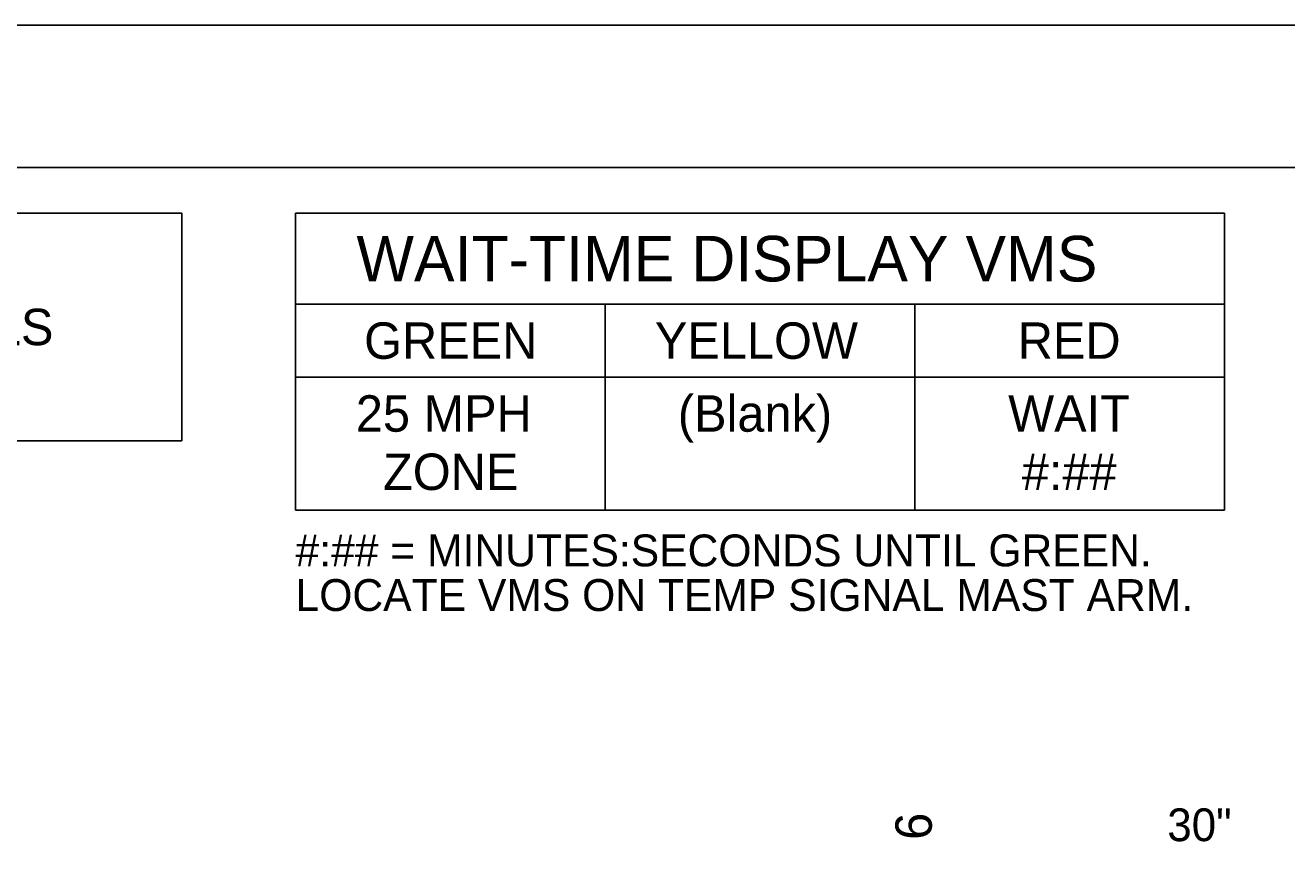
# Model space of a CAD drawing. Extents: x 99977 to 100176, y 99905 to 100011.
# Drawn here: x 100082.228 to 100084.999, y 100008.89 to 100010.687 of the extents above; entities that cross this region are included whole.
import ezdxf

# ---------------------------------------------------------------- set-up
doc = ezdxf.new("R2010")
doc.units = 0
for name, color, linetype in [('SH_GI_PlotLimits', 7, 'Continuous'), ('SH_GI_SheetBorder', 7, 'Continuous'), ('SH_TI_Tables', 7, 'Continuous'), ('TR_SN_ConstructionSigns', 7, 'Continuous'), ('TR_WZ_PortableChangeMessageSign', 7, 'Continuous'), ('TR_WZ_WorkZoneTextCurrent', 7, 'Continuous')]:
    doc.layers.add(name, color=color, linetype=linetype)

msp = doc.modelspace()

# ---------------------------------------------------------------- linework, layer by layer
at = {"layer": 'SH_GI_PlotLimits'}
msp.add_lwpolyline([(100079.0625, 99999.6875), (100096.0625, 99999.6875), (100096.0625, 100010.6875), (100079.0625, 100010.6875)], close=True, dxfattribs=at)
at = {"layer": 'SH_GI_SheetBorder'}
msp.add_line((100080, 100010.375), (100095.75, 100010.375), dxfattribs=at)
at = {"layer": 'SH_TI_Tables'}
msp.add_lwpolyline([(100080.1, 100010.275), (100082.5718, 100010.275), (100082.5718, 100009.775), (100080.1, 100009.775)], close=True, dxfattribs=at)
at = {"layer": 'TR_WZ_PortableChangeMessageSign'}
for p, q in [((100082.8218, 100010.275), (100084.8618, 100010.275)), ((100082.8218, 100009.6227), (100082.8218, 100010.275)), ((100084.8618, 100009.6227), (100084.8618, 100010.275)), ((100084.8618, 100010.075), (100082.8218, 100010.075)), ((100083.5018, 100009.6227), (100083.5018, 100010.075)), ((100084.1818, 100009.6227), (100084.1818, 100010.075)), ((100083.5018, 100009.915), (100082.8218, 100009.915)), ((100084.1818, 100009.915), (100083.5018, 100009.915)), ((100084.8618, 100009.915), (100084.1818, 100009.915)), ((100084.8618, 100009.6227), (100082.8218, 100009.6227))]:
    msp.add_line(p, q, dxfattribs=at)

# ---------------------------------------------------------------- texts
at = {"layer": 'SH_TI_Tables'}
msp.add_text('AND INTERSECTING ROADWAY DETAILS', height=0.08, rotation=360, dxfattribs=at).set_placement((100080.18, 100009.985))
at = {"layer": 'TR_SN_ConstructionSigns'}
msp.add_text('30"', height=0.072, rotation=360, dxfattribs=at).set_placement((100084.7363, 100008.8959))
at = {"layer": 'TR_WZ_PortableChangeMessageSign'}
for s, height, p in [('WAIT-TIME DISPLAY VMS', 0.1, (100082.9556, 100010.125)), ('GREEN', 0.08, (100082.9724, 100009.955)), ('YELLOW', 0.08, (100083.6109, 100009.955)), ('RED', 0.08, (100084.4078, 100009.955)), ('(Blank)', 0.08, (100083.6614, 100009.795)), ('25 MPH', 0.08, (100082.9542, 100009.795)), ('WAIT', 0.08, (100084.3868, 100009.795)), ('ZONE', 0.08, (100083.0139, 100009.667)), ('#:##', 0.08, (100084.4169, 100009.667)), ('#:## = MINUTES:SECONDS UNTIL GREEN.', 0.07, (100082.8218, 100009.4993)), ('LOCATE VMS ON TEMP SIGNAL MAST ARM.', 0.07, (100082.8218, 100009.4013))]:
    msp.add_text(s, height=height, rotation=360, dxfattribs=at).set_placement(p)
at = {"layer": 'TR_WZ_WorkZoneTextCurrent'}
msp.add_text('6', height=0.08, rotation=90, dxfattribs=at).set_placement((100084.2191, 100008.8988))

doc.saveas('drawing.dxf')
